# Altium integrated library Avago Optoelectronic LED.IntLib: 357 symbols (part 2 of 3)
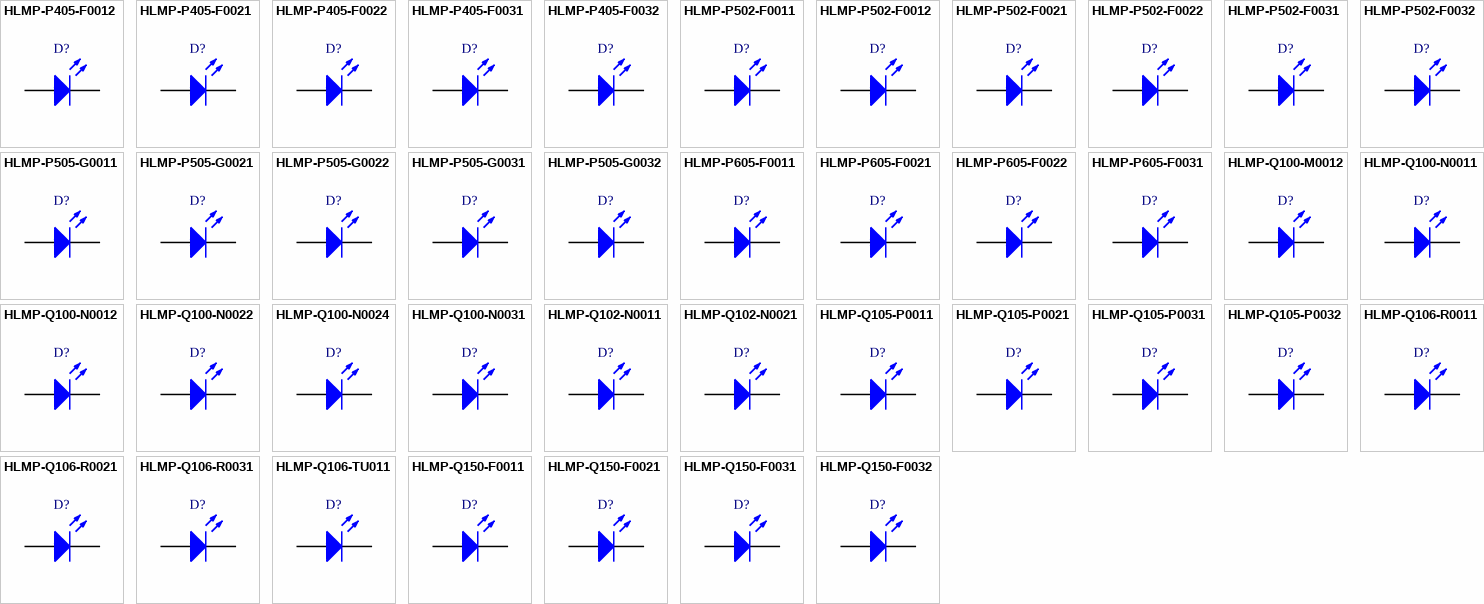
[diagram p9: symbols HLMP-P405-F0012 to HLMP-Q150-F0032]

## HLMP-Q100-N0012
designator D?
Subminiature Red LED Lamp; LuminousIntensity: 25mcd (Minimum).; PCB_Layout: Complies with manufacturer's recommendation.
footprint 2.2X2.1X2.9 (SM LED; 2 Gull Wing Leads; Body 2.2 x 2.1 mm, (LxW))
simulation model Agl_HLMPQ100 (Diode)
signal-integrity model LED
pins: 1 A, 2 K

## HLMP-Q100-N0022
designator D?
Subminiature Red LED Lamp; LuminousIntensity: 25mcd (Minimum).; PCB_Layout: Complies with manufacturer's recommendation.; DrillSize: Nominal, Rounded to nearest 0.05mm
footprint 2.2X2.1X2.9Y (SM LED; 2 Yoke Leads)
simulation model Agl_HLMPQ100 (Diode)
signal-integrity model LED
pins: 1 A, 2 K

## HLMP-Q100-N0024
designator D?
Subminiature Red LED Lamp; LuminousIntensity: 25mcd (Minimum).; PCB_Layout: Complies with manufacturer's recommendation.; DrillSize: Nominal, Rounded to nearest 0.05mm
footprint 2.2X2.1X2.9Y (SM LED; 2 Yoke Leads)
simulation model Agl_HLMPQ100 (Diode)
signal-integrity model LED
pins: 1 A, 2 K

## HLMP-Q100-N0031
designator D?
Subminiature Red LED Lamp; LuminousIntensity: 25mcd (Minimum).; PCB_Layout: Complies with manufacturer's recommendation.; DrillSize: Nominal, Rounded to nearest 0.05mm
footprint 2.2X2.1X2.9Z (SM LED; 2 Z-Bend Leads)
simulation model Agl_HLMPQ100 (Diode)
signal-integrity model LED
pins: 1 A, 2 K

## HLMP-Q102-N0011
designator D?
Subminiature High Performance TS AlGaAs Red LED Lamp; LuminousIntensity: 25mcd (Minimum).; PCB_Layout: Complies with manufacturer's recommendation.
footprint 2.2X2.1X2.9 (SM LED; 2 Gull Wing Leads; Body 2.2 x 2.1 mm, (LxW))
simulation model Agl_HLMPQ102 (Diode)
signal-integrity model LED
pins: 1 A, 2 K

## HLMP-Q102-N0021
designator D?
Subminiature High Performance TS AlGaAs Red LED Lamp; LuminousIntensity: 25mcd (Minimum).; PCB_Layout: Complies with manufacturer's recommendation.; DrillSize: Nominal, Rounded to nearest 0.05mm
footprint 2.2X2.1X2.9Y (SM LED; 2 Yoke Leads)
simulation model Agl_HLMPQ102 (Diode)
signal-integrity model LED
pins: 1 A, 2 K

## HLMP-Q105-P0011
designator D?
Subminiature Red LED Lamp; LuminousIntensity: 40mcd (Minimum).; PCB_Layout: Complies with manufacturer's recommendation.
footprint 2.2X2.1X2.9 (SM LED; 2 Gull Wing Leads; Body 2.2 x 2.1 mm, (LxW))
simulation model Agl_HLMPQ100 (Diode)
signal-integrity model LED
pins: 1 A, 2 K

## HLMP-Q105-P0021
designator D?
Subminiature Red LED Lamp; LuminousIntensity: 40mcd (Minimum).; PCB_Layout: Complies with manufacturer's recommendation.; DrillSize: Nominal, Rounded to nearest 0.05mm
footprint 2.2X2.1X2.9Y (SM LED; 2 Yoke Leads)
simulation model Agl_HLMPQ100 (Diode)
signal-integrity model LED
pins: 1 A, 2 K

## HLMP-Q105-P0031
designator D?
Subminiature Red LED Lamp; LuminousIntensity: 40mcd (Minimum).; PCB_Layout: Complies with manufacturer's recommendation.; DrillSize: Nominal, Rounded to nearest 0.05mm
footprint 2.2X2.1X2.9Z (SM LED; 2 Z-Bend Leads)
simulation model Agl_HLMPQ100 (Diode)
signal-integrity model LED
pins: 1 A, 2 K

## HLMP-Q105-P0032
designator D?
Subminiature Red LED Lamp; LuminousIntensity: 40mcd (Minimum).; PCB_Layout: Complies with manufacturer's recommendation.; DrillSize: Nominal, Rounded to nearest 0.05mm
footprint 2.2X2.1X2.9Z (SM LED; 2 Z-Bend Leads)
simulation model Agl_HLMPQ100 (Diode)
signal-integrity model LED
pins: 1 A, 2 K

## HLMP-Q106-R0011
designator D?
Subminiature High Performance TS AlGaAs Red LED Lamp; LuminousIntensity: 100mcd (Minimum).; PCB_Layout: Complies with manufacturer's recommendation.
footprint 2.2X2.1X2.9 (SM LED; 2 Gull Wing Leads; Body 2.2 x 2.1 mm, (LxW))
simulation model Agl_HLMPQ102 (Diode)
signal-integrity model LED
pins: 1 A, 2 K

## HLMP-Q106-R0021
designator D?
Subminiature High Performance TS AlGaAs Red LED Lamp; LuminousIntensity: 100mcd (Minimum).; PCB_Layout: Complies with manufacturer's recommendation.; DrillSize: Nominal, Rounded to nearest 0.05mm
footprint 2.2X2.1X2.9Y (SM LED; 2 Yoke Leads)
simulation model Agl_HLMPQ102 (Diode)
signal-integrity model LED
pins: 1 A, 2 K

## HLMP-Q106-R0031
designator D?
Subminiature High Performance TS AlGaAs Red LED Lamp; LuminousIntensity: 100mcd (Minimum).; PCB_Layout: Complies with manufacturer's recommendation.; DrillSize: Nominal, Rounded to nearest 0.05mm
footprint 2.2X2.1X2.9Z (SM LED; 2 Z-Bend Leads)
simulation model Agl_HLMPQ102 (Diode)
signal-integrity model LED
pins: 1 A, 2 K

## HLMP-Q106-TU011
designator D?
Subminiature High Performance TS AlGaAs Red LED Lamp; LuminousIntensity: 250mcd (Minimum).; PCB_Layout: Complies with manufacturer's recommendation.
footprint 2.2X2.1X2.9 (SM LED; 2 Gull Wing Leads; Body 2.2 x 2.1 mm, (LxW))
simulation model Agl_HLMPQ102 (Diode)
signal-integrity model LED
pins: 1 A, 2 K

## HLMP-Q150-F0011
designator D?
Subminiature Red LED Lamp; LuminousIntensity: 1mcd (Minimum).; PCB_Layout: Complies with manufacturer's recommendation.
footprint 2.2X2.1X2.9 (SM LED; 2 Gull Wing Leads; Body 2.2 x 2.1 mm, (LxW))
simulation model Agl_HLMPQ150 (Diode)
signal-integrity model LED
pins: 1 A, 2 K

## HLMP-Q150-F0021
designator D?
Subminiature Red LED Lamp; LuminousIntensity: 1mcd (Minimum).; PCB_Layout: Complies with manufacturer's recommendation.; DrillSize: Nominal, Rounded to nearest 0.05mm
footprint 2.2X2.1X2.9Y (SM LED; 2 Yoke Leads)
simulation model Agl_HLMPQ150 (Diode)
signal-integrity model LED
pins: 1 A, 2 K

## HLMP-Q150-F0031
designator D?
Subminiature Red LED Lamp; LuminousIntensity: 1mcd (Minimum).; PCB_Layout: Complies with manufacturer's recommendation.; DrillSize: Nominal, Rounded to nearest 0.05mm
footprint 2.2X2.1X2.9Z (SM LED; 2 Z-Bend Leads)
simulation model Agl_HLMPQ150 (Diode)
signal-integrity model LED
pins: 1 A, 2 K

## HLMP-Q150-F0032
designator D?
Subminiature Red LED Lamp; LuminousIntensity: 1mcd (Minimum).; PCB_Layout: Complies with manufacturer's recommendation.; DrillSize: Nominal, Rounded to nearest 0.05mm
footprint 2.2X2.1X2.9Z (SM LED; 2 Z-Bend Leads)
simulation model Agl_HLMPQ150 (Diode)
signal-integrity model LED
pins: 1 A, 2 K

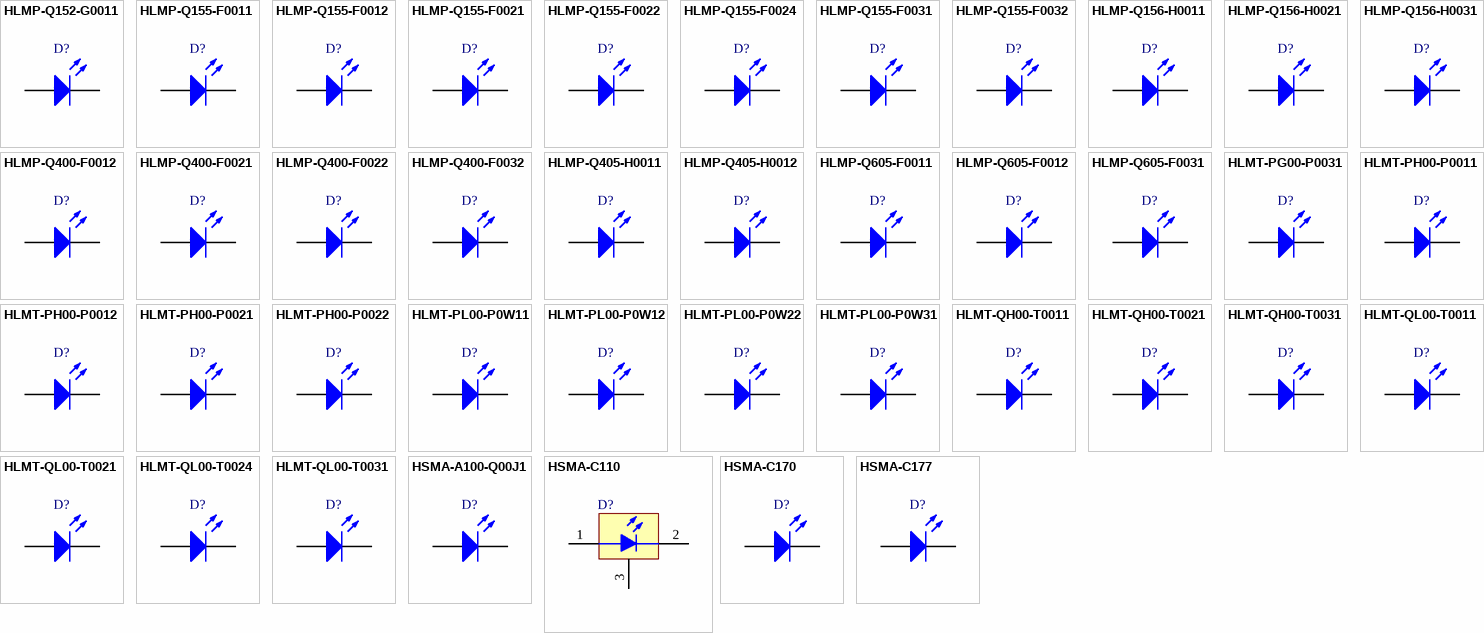
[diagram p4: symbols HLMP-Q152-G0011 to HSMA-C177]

## HLMP-Q152-G0011
designator D?
Subminiature High Performance TS AlGaAs Red LED Lamp; LuminousIntensity: 1mcd (Minimum).; PCB_Layout: Complies with manufacturer's recommendation.
footprint 2.2X2.1X2.9 (SM LED; 2 Gull Wing Leads; Body 2.2 x 2.1 mm, (LxW))
simulation model Agl_HLMPQ152 (Diode)
signal-integrity model LED
pins: 1 A, 2 K

## HLMP-Q155-F0011
designator D?
Subminiature Red LED Lamp; LuminousIntensity: 1mcd (Minimum).; PCB_Layout: Complies with manufacturer's recommendation.
footprint 2.2X2.1X2.9 (SM LED; 2 Gull Wing Leads; Body 2.2 x 2.1 mm, (LxW))
simulation model Agl_HLMPQ150 (Diode)
signal-integrity model LED
pins: 1 A, 2 K

## HLMP-Q155-F0012
designator D?
Subminiature Red LED Lamp; LuminousIntensity: 1mcd (Minimum).; PCB_Layout: Complies with manufacturer's recommendation.
footprint 2.2X2.1X2.9 (SM LED; 2 Gull Wing Leads; Body 2.2 x 2.1 mm, (LxW))
simulation model Agl_HLMPQ150 (Diode)
signal-integrity model LED
pins: 1 A, 2 K

## HLMP-Q155-F0021
designator D?
Subminiature Red LED Lamp; LuminousIntensity: 1mcd (Minimum).; PCB_Layout: Complies with manufacturer's recommendation.; DrillSize: Nominal, Rounded to nearest 0.05mm
footprint 2.2X2.1X2.9Y (SM LED; 2 Yoke Leads)
simulation model Agl_HLMPQ150 (Diode)
signal-integrity model LED
pins: 1 A, 2 K

## HLMP-Q155-F0022
designator D?
Subminiature Red LED Lamp; LuminousIntensity: 1mcd (Minimum).; PCB_Layout: Complies with manufacturer's recommendation.; DrillSize: Nominal, Rounded to nearest 0.05mm
footprint 2.2X2.1X2.9Y (SM LED; 2 Yoke Leads)
simulation model Agl_HLMPQ150 (Diode)
signal-integrity model LED
pins: 1 A, 2 K

## HLMP-Q155-F0024
designator D?
Subminiature Red LED Lamp; LuminousIntensity: 1mcd (Minimum).; PCB_Layout: Complies with manufacturer's recommendation.; DrillSize: Nominal, Rounded to nearest 0.05mm
footprint 2.2X2.1X2.9Y (SM LED; 2 Yoke Leads)
simulation model Agl_HLMPQ150 (Diode)
signal-integrity model LED
pins: 1 A, 2 K

## HLMP-Q155-F0031
designator D?
Subminiature Red LED Lamp; LuminousIntensity: 1mcd (Minimum).; PCB_Layout: Complies with manufacturer's recommendation.; DrillSize: Nominal, Rounded to nearest 0.05mm
footprint 2.2X2.1X2.9Z (SM LED; 2 Z-Bend Leads)
simulation model Agl_HLMPQ150 (Diode)
signal-integrity model LED
pins: 1 A, 2 K

## HLMP-Q155-F0032
designator D?
Subminiature Red LED Lamp; LuminousIntensity: 1mcd (Minimum).; PCB_Layout: Complies with manufacturer's recommendation.; DrillSize: Nominal, Rounded to nearest 0.05mm
footprint 2.2X2.1X2.9Z (SM LED; 2 Z-Bend Leads)
simulation model Agl_HLMPQ150 (Diode)
signal-integrity model LED
pins: 1 A, 2 K

## HLMP-Q156-H0011
designator D?
Subminiature High Performance TS AlGaAs Red LED Lamp; LuminousIntensity: 2.5mcd (Minimum).; PCB_Layout: Complies with manufacturer's recommendation.
footprint 2.2X2.1X2.9 (SM LED; 2 Gull Wing Leads; Body 2.2 x 2.1 mm, (LxW))
simulation model Agl_HLMPQ152 (Diode)
signal-integrity model LED
pins: 1 A, 2 K

## HLMP-Q156-H0021
designator D?
Subminiature High Performance TS AlGaAs Red LED Lamp; LuminousIntensity: 2.5mcd (Minimum).; PCB_Layout: Complies with manufacturer's recommendation.; DrillSize: Nominal, Rounded to nearest 0.05mm
footprint 2.2X2.1X2.9Y (SM LED; 2 Yoke Leads)
simulation model Agl_HLMPQ152 (Diode)
signal-integrity model LED
pins: 1 A, 2 K

## HLMP-Q156-H0031
designator D?
Subminiature High Performance TS AlGaAs Red LED Lamp; LuminousIntensity: 2.5mcd (Minimum).; PCB_Layout: Complies with manufacturer's recommendation.; DrillSize: Nominal, Rounded to nearest 0.05mm
footprint 2.2X2.1X2.9Z (SM LED; 2 Z-Bend Leads)
simulation model Agl_HLMPQ152 (Diode)
signal-integrity model LED
pins: 1 A, 2 K

## HLMP-Q400-F0012
designator D?
Subminiature Orange LED Lamp; LuminousIntensity: 1mcd (Minimum).; PCB_Layout: Complies with manufacturer's recommendation.
footprint 2.2X2.1X2.9 (SM LED; 2 Gull Wing Leads; Body 2.2 x 2.1 mm, (LxW))
simulation model Agl_HLMPQ400 (Diode)
signal-integrity model LED
pins: 1 A, 2 K

## HLMP-Q400-F0021
designator D?
Subminiature Orange LED Lamp; LuminousIntensity: 1mcd (Minimum).; PCB_Layout: Complies with manufacturer's recommendation.; DrillSize: Nominal, Rounded to nearest 0.05mm
footprint 2.2X2.1X2.9Y (SM LED; 2 Yoke Leads)
simulation model Agl_HLMPQ400 (Diode)
signal-integrity model LED
pins: 1 A, 2 K

## HLMP-Q400-F0022
designator D?
Subminiature Orange LED Lamp; LuminousIntensity: 1mcd (Minimum).; PCB_Layout: Complies with manufacturer's recommendation.; DrillSize: Nominal, Rounded to nearest 0.05mm
footprint 2.2X2.1X2.9Y (SM LED; 2 Yoke Leads)
simulation model Agl_HLMPQ400 (Diode)
signal-integrity model LED
pins: 1 A, 2 K

## HLMP-Q400-F0032
designator D?
Subminiature Orange LED Lamp; LuminousIntensity: 1mcd (Minimum).; PCB_Layout: Complies with manufacturer's recommendation.; DrillSize: Nominal, Rounded to nearest 0.05mm
footprint 2.2X2.1X2.9Z (SM LED; 2 Z-Bend Leads)
simulation model Agl_HLMPQ400 (Diode)
signal-integrity model LED
pins: 1 A, 2 K

## HLMP-Q405-H0011
designator D?
Subminiature Orange LED Lamp; LuminousIntensity: 2.5mcd (Minimum).; PCB_Layout: Complies with manufacturer's recommendation.
footprint 2.2X2.1X2.9 (SM LED; 2 Gull Wing Leads; Body 2.2 x 2.1 mm, (LxW))
simulation model Agl_HLMPQ400 (Diode)
signal-integrity model LED
pins: 1 A, 2 K

## HLMP-Q405-H0012
designator D?
Subminiature Orange LED Lamp; LuminousIntensity: 2.5mcd (Minimum).; PCB_Layout: Complies with manufacturer's recommendation.
footprint 2.2X2.1X2.9 (SM LED; 2 Gull Wing Leads; Body 2.2 x 2.1 mm, (LxW))
simulation model Agl_HLMPQ400 (Diode)
signal-integrity model LED
pins: 1 A, 2 K

## HLMP-Q605-F0011
designator D?
Subminiature Green LED Lamp; LuminousIntensity: 1mcd (Minimum).; PCB_Layout: Complies with manufacturer's recommendation.
footprint 2.2X2.1X2.9 (SM LED; 2 Gull Wing Leads; Body 2.2 x 2.1 mm, (LxW))
simulation model Agl_HLMPQ605 (Diode)
signal-integrity model LED
pins: 1 A, 2 K

## HLMP-Q605-F0012
designator D?
Subminiature Green LED Lamp; LuminousIntensity: 1mcd (Minimum).; PCB_Layout: Complies with manufacturer's recommendation.
footprint 2.2X2.1X2.9 (SM LED; 2 Gull Wing Leads; Body 2.2 x 2.1 mm, (LxW))
simulation model Agl_HLMPQ605 (Diode)
signal-integrity model LED
pins: 1 A, 2 K

## HLMP-Q605-F0031
designator D?
Subminiature Green LED Lamp; LuminousIntensity: 1mcd (Minimum).; PCB_Layout: Complies with manufacturer's recommendation.; DrillSize: Nominal, Rounded to nearest 0.05mm
footprint 2.2X2.1X2.9Z (SM LED; 2 Z-Bend Leads)
simulation model Agl_HLMPQ605 (Diode)
signal-integrity model LED
pins: 1 A, 2 K

## HLMT-PG00-P0031
designator D?
Subminiature High Performance TS AlInGaP Red LED Lamp; LuminousIntensity: 40mcd (Minimum).; PCB_Layout: Complies with manufacturer's recommendation.; DrillSize: Nominal, Rounded to nearest 0.05mm
footprint 2.2X2.1X2.2Z (SM LED; 2 Z-Bend Leads)
simulation model Agl_HLMTPH00 (Diode)
signal-integrity model LED
pins: 1 A, 2 K

## HLMT-PH00-P0011
designator D?
Subminiature High Performance TS AlInGaP Red/Orange LED Lamp; LuminousIntensity: 40mcd (Minimum).; LED_Colour: Red & Orange; PCB_Layout: Complies with manufacturer's recommendation.
footprint 2.2X2.1X2.2 (SM LED; 2 Gull Wing Leads; Body 2.2 x 2.1 mm, (LxW))
simulation model Agl_HLMTPH00 (Diode)
signal-integrity model LED
pins: 1 A, 2 K

## HLMT-PH00-P0012
designator D?
Subminiature High Performance TS AlInGaP Red/Orange LED Lamp; LuminousIntensity: 40mcd (Minimum).; LED_Colour: Red & Orange; PCB_Layout: Complies with manufacturer's recommendation.
footprint 2.2X2.1X2.2 (SM LED; 2 Gull Wing Leads; Body 2.2 x 2.1 mm, (LxW))
simulation model Agl_HLMTPH00 (Diode)
signal-integrity model LED
pins: 1 A, 2 K

## HLMT-PH00-P0021
designator D?
Subminiature High Performance AlInGaP Red/Orange LED Lamp; LuminousIntensity: 40mcd (Minimum).; LED_Colour: Red & Orange; PCB_Layout: Complies with manufacturer's recommendation.; DrillSize: Nominal, Rounded to nearest 0.05mm
footprint 2.2X2.1X2.2Y (SM LED; 2 Yoke Leads)
simulation model Agl_HLMTPH00 (Diode)
signal-integrity model LED
pins: 1 A, 2 K

## HLMT-PH00-P0022
designator D?
Subminiature High Performance AlInGaP Red/Orange LED Lamp; LuminousIntensity: 40mcd (Minimum).; LED_Colour: Red & Orange; PCB_Layout: Complies with manufacturer's recommendation.; DrillSize: Nominal, Rounded to nearest 0.05mm
footprint 2.2X2.1X2.2Y (SM LED; 2 Yoke Leads)
simulation model Agl_HLMTPH00 (Diode)
signal-integrity model LED
pins: 1 A, 2 K

## HLMT-PL00-P0W11
designator D?
Subminiature High Performance TS AlInGaP Amber LED Lamp; LuminousIntensity: 40mcd (Minimum).; PCB_Layout: Complies with manufacturer's recommendation.
footprint 2.2X2.1X2.2 (SM LED; 2 Gull Wing Leads; Body 2.2 x 2.1 mm, (LxW))
simulation model Agl_HLMTPH00 (Diode)
signal-integrity model LED
pins: 1 A, 2 K

## HLMT-PL00-P0W12
designator D?
Subminiature High Performance AlInGaP Amber LED Lamp; LuminousIntensity: 40mcd (Minimum).; PCB_Layout: Complies with manufacturer's recommendation.
footprint 2.2X2.1X2.2 (SM LED; 2 Gull Wing Leads; Body 2.2 x 2.1 mm, (LxW))
simulation model Agl_HLMTPH00 (Diode)
signal-integrity model LED
pins: 1 A, 2 K

## HLMT-PL00-P0W22
designator D?
Subminiature High Performance AlInGaP Amber LED Lamp; LuminousIntensity: 40mcd (Minimum).; PCB_Layout: Complies with manufacturer's recommendation.; DrillSize: Nominal, Rounded to nearest 0.05mm
footprint 2.2X2.1X2.2Y (SM LED; 2 Yoke Leads)
simulation model Agl_HLMTPH00 (Diode)
signal-integrity model LED
pins: 1 A, 2 K

## HLMT-PL00-P0W31
designator D?
Subminiature High Performance AlInGaP Amber LED Lamp; LuminousIntensity: 40mcd (Minimum).; PCB_Layout: Complies with manufacturer's recommendation.; DrillSize: Nominal, Rounded to nearest 0.05mm
footprint 2.2X2.1X2.2Z (SM LED; 2 Z-Bend Leads)
simulation model Agl_HLMTPH00 (Diode)
signal-integrity model LED
pins: 1 A, 2 K

## HLMT-QH00-T0011
designator D?
Subminiature High Performance AlInGaP Red/Orange LED Lamp; LuminousIntensity: 250mcd (Minimum).; LED_Colour: Red & Orange; PCB_Layout: Complies with manufacturer's recommendation.
footprint 2.2X2.1X2.9 (SM LED; 2 Gull Wing Leads; Body 2.2 x 2.1 mm, (LxW))
simulation model Agl_HLMTPH00 (Diode)
signal-integrity model LED
pins: 1 A, 2 K

## HLMT-QH00-T0021
designator D?
Subminiature High Performance AlInGaP Red/Orange LED Lamp; LuminousIntensity: 250mcd (Minimum).; LED_Colour: Red & Orange; PCB_Layout: Complies with manufacturer's recommendation.; DrillSize: Nominal, Rounded to nearest 0.05mm
footprint 2.2X2.1X2.9Y (SM LED; 2 Yoke Leads)
simulation model Agl_HLMTPH00 (Diode)
signal-integrity model LED
pins: 1 A, 2 K

## HLMT-QH00-T0031
designator D?
Subminiature High Performance AlInGaP Red/Orange LED Lamp; LuminousIntensity: 250mcd (Minimum).; LED_Colour: Red & Orange; PCB_Layout: Complies with manufacturer's recommendation.; DrillSize: Nominal, Rounded to nearest 0.05mm
footprint 2.2X2.1X2.9Z (SM LED; 2 Z-Bend Leads)
simulation model Agl_HLMTPH00 (Diode)
signal-integrity model LED
pins: 1 A, 2 K

## HLMT-QL00-T0011
designator D?
Subminiature High Performance AlInGaP Amber LED Lamp; LuminousIntensity: 250mcd (Minimum).; PCB_Layout: Complies with manufacturer's recommendation.
footprint 2.2X2.1X2.9 (SM LED; 2 Gull Wing Leads; Body 2.2 x 2.1 mm, (LxW))
simulation model Agl_HLMTPH00 (Diode)
signal-integrity model LED
pins: 1 A, 2 K

## HLMT-QL00-T0021
designator D?
Subminiature High Performance AlInGaP Amber LED Lamp; LuminousIntensity: 250mcd (Minimum).; PCB_Layout: Complies with manufacturer's recommendation.; DrillSize: Nominal, Rounded to nearest 0.05mm
footprint 2.2X2.1X2.9Y (SM LED; 2 Yoke Leads)
simulation model Agl_HLMTPH00 (Diode)
signal-integrity model LED
pins: 1 A, 2 K

## HLMT-QL00-T0024
designator D?
Subminiature High Performance AlInGaP Amber LED Lamp; LuminousIntensity: 250mcd (Minimum).; PCB_Layout: Complies with manufacturer's recommendation.; DrillSize: Nominal, Rounded to nearest 0.05mm
footprint 2.2X2.1X2.9Y (SM LED; 2 Yoke Leads)
simulation model Agl_HLMTPH00 (Diode)
signal-integrity model LED
pins: 1 A, 2 K

## HLMT-QL00-T0031
designator D?
Subminiature High Performance AlInGaP Amber LED Lamp; LuminousIntensity: 250mcd (Minimum).; PCB_Layout: Complies with manufacturer's recommendation.; DrillSize: Nominal, Rounded to nearest 0.05mm
footprint 2.2X2.1X2.9Z (SM LED; 2 Z-Bend Leads)
simulation model Agl_HLMTPH00 (Diode)
signal-integrity model LED
pins: 1 A, 2 K

## HSMA-A100-Q00J1
designator D?
Surface Mount LED Indicator, Amber; LuminousIntensity: 63mcd (Minimum).; PCB_Layout: Complies with manufacturer's recommendation.
footprint 3.5X2.8X1.9 (SM LED; 2 C-Bend Leads; Body 3.5 x 2.8 x 1.9 mm, inc leads (LxWxH typ))
simulation model Agl_HSMAC191 (Diode)
signal-integrity model LED
pins: 1 A, 2 K

## HSMA-C110
designator D?
High Performance Chip LED, Amber; LuminousIntensity: 25mcd (Minimum).; PCB_Layout: Complies with manufacturer's recommendation.
footprint 3.2X1.0X1.5 (SM Right-Angle Mount LED; 3 Leads; Body 3.2 x 1.0 x 1.5 mm (LxWxH))
simulation model Agl_HSMAC191 (Diode)
pins: 1 A, 2 K, 3 Mount

## HSMA-C170
designator D?
High Performance Chip LED, Amber; LuminousIntensity: 25mcd (Minimum).; PCB_Layout: Complies with manufacturer's recommendation.
footprint 2.0X1.25X0.8 (SM LED; 2 Flat Leads)
simulation model Agl_HSMAC191 (Diode)
signal-integrity model LED
pins: 1 A, 2 K

## HSMA-C177
designator D?
Low Profile Chip LED, Amber; LuminousIntensity: 25mcd (Minimum).; PCB_Layout: Complies with manufacturer's recommendation.
footprint 2.1X1.25X0.4 (SM LED; 2 Flat Leads)
simulation model Agl_HSMAC177 (Diode)
signal-integrity model LED
pins: 1 A, 2 K

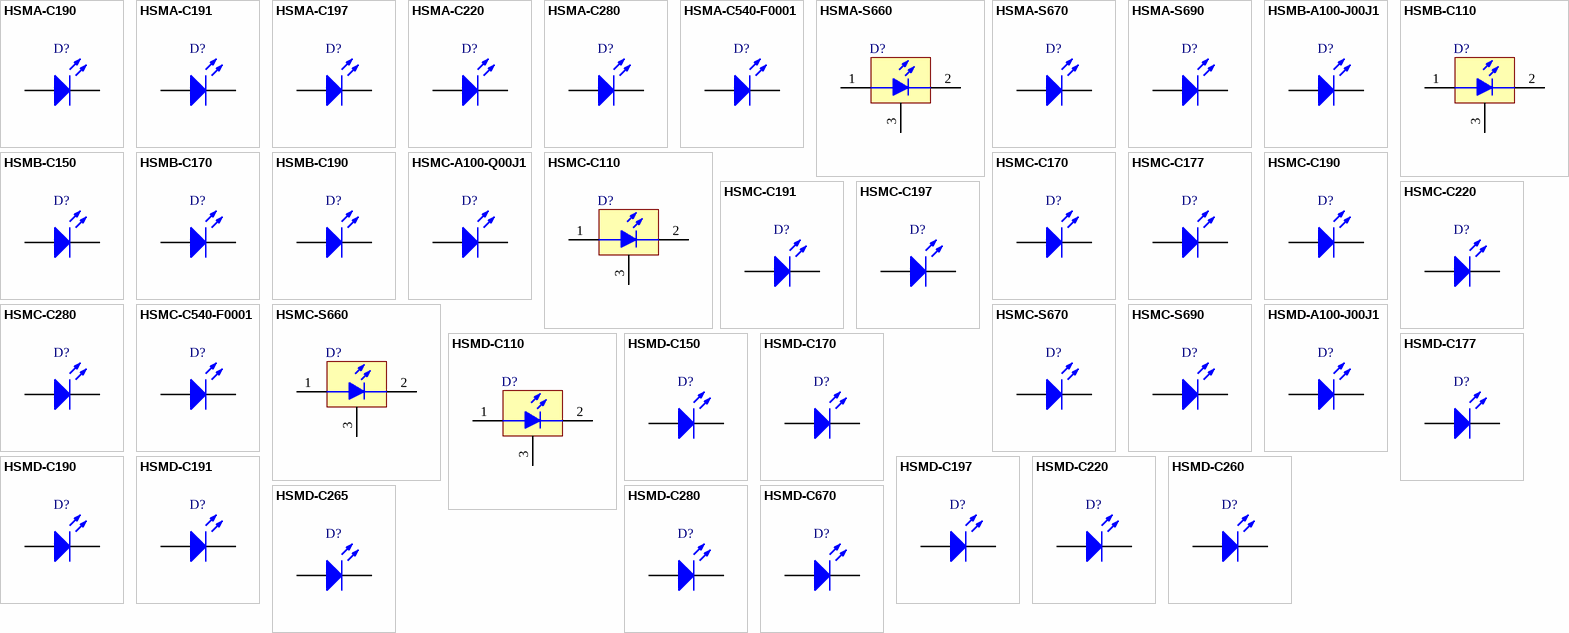
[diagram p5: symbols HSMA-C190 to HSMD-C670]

## HSMA-C190
designator D?
High Performance Chip LED, Amber; LuminousIntensity: 25mcd (Minimum).; PCB_Layout: Complies with manufacturer's recommendation.
footprint 1.6X0.8X0.8 (SM LED; 2 Flat Leads)
simulation model Agl_HSMAC191 (Diode)
signal-integrity model LED
pins: 1 A, 2 K

## HSMA-C191
designator D?
High Performance Chip LED, Amber; LuminousIntensity: 25mcd (Minimum).; PCB_Layout: Complies with manufacturer's recommendation.
footprint 1.6X0.8X0.6 (SM LED; 2 Flat Leads)
simulation model Agl_HSMAC191 (Diode)
signal-integrity model LED
pins: 1 A, 2 K

## HSMA-C197
designator D?
Low Profile Chip LED, Yellow; LuminousIntensity: 2.5mcd (Minimum).; PCB_Layout: Complies with manufacturer's recommendation.
footprint 1.6X0.8X0.4 (SM LED; 2 Flat Leads)
simulation model Agl_HSMAC177 (Diode)
signal-integrity model LED
pins: 1 A, 2 K

## HSMA-C220
designator D?
High Performance Chip LED, Amber; LuminousIntensity: 63mcd (Minimum).; PCB_Layout: Complies with manufacturer's recommendation.
footprint 2.0X1.25X1.2 (SM LED; 2 Flat Leads)
simulation model Agl_HSMAC220 (Diode)
signal-integrity model LED
pins: 1 A, 2 K

## HSMA-C280
designator D?
Miniature Chip LED, Amber; LuminousIntensity: 25mcd (Minimum).; PCB_Layout: Complies with manufacturer's recommendation.
footprint 1.0X0.5X0.4 (SM LED; 2 Flat Leads)
simulation model Agl_HSMAC177 (Diode)
signal-integrity model LED
pins: 1 A, 2 K

## HSMA-C540-F0001
designator D?
Top Mount AS AlInGaP Amber Oval Lens High Brightness; LuminousIntensity: 96mcd (Minimum).; PCB_Layout: Complies with manufacturer's recommendation.
footprint 2.0X1.25X1.2 (SM LED; 2 Flat Leads)
simulation model Agl_HSMAC540 (Diode)
signal-integrity model LED
pins: 1 A, 2 K

## HSMA-S660
designator D?
Right Angle SMT Chip LED, Amber; LuminousIntensity: 16mcd (Minimum).; PCB_Layout: Complies with manufacturer's recommendation.
footprint NA (SM Right-Angle Mount LED; 3 Leads)
simulation model Agl_HSMAC191 (Diode)
pins: 1 A, 2 K, 3 Mount

## HSMA-S670
designator D?
SMT Top Mount Chip LED, Amber; LuminousIntensity: 16mcd (Minimum).; PCB_Layout: Complies with manufacturer's recommendation.
footprint 2.0X1.25X0.8 (SM LED; 2 Flat Leads)
simulation model Agl_HSMAC191 (Diode)
signal-integrity model LED
pins: 1 A, 2 K

## HSMA-S690
designator D?
SMT Top Mount Chip LED, Amber; LuminousIntensity: 16mcd (Minimum).; PCB_Layout: Complies with manufacturer's recommendation.
footprint 1.6X0.8X0.7 (SM LED; 2 Flat Leads)
simulation model Agl_HSMAC191 (Diode)
signal-integrity model LED
pins: 1 A, 2 K

## HSMB-A100-J00J1
designator D?
Surface Mount LED Indicator, Blue; LuminousIntensity: 4mcd (Minimum).; PCB_Layout: Complies with manufacturer's recommendation.
footprint 3.5X2.8X1.9 (SM LED; 2 C-Bend Leads; Body 3.5 x 2.8 x 1.9 mm, inc leads (LxWxH typ))
simulation model Agl_HSMBA100 (Diode)
signal-integrity model LED
pins: 1 A, 2 K

## HSMB-C110
designator D?
Blue Surface Mount Chip LED, Blue; LuminousIntensity: 1.6mcd (Minimum).; PCB_Layout: Complies with manufacturer's recommendation.
footprint 3.2X1.0X1.5 (SM Right-Angle Mount LED; 3 Leads; Body 3.2 x 1.0 x 1.5 mm (LxWxH))
simulation model Agl_HSMBC110 (Diode)
pins: 1 A, 2 K, 3 Mount

## HSMB-C150
designator D?
Blue Surface Mount Chip LED, Blue; LuminousIntensity: 1.6mcd (Minimum).; PCB_Layout: Complies with manufacturer's recommendation.
footprint 3.2X1.6X1.1 (SM LED; 2 Flat Leads)
simulation model Agl_HSMBC110 (Diode)
signal-integrity model LED
pins: 1 A, 2 K

## HSMB-C170
designator D?
Blue Surface Mount Chip LED, Blue; LuminousIntensity: 1.6mcd (Minimum).; PCB_Layout: Complies with manufacturer's recommendation.
footprint 2.0X1.25X0.8 (SM LED; 2 Flat Leads)
simulation model Agl_HSMBC110 (Diode)
signal-integrity model LED
pins: 1 A, 2 K

## HSMB-C190
designator D?
Blue Surface Mount Chip LED, Blue; LuminousIntensity: 1.6mcd (Minimum).; PCB_Layout: Complies with manufacturer's recommendation.
footprint 1.6X0.8X0.8 (SM LED; 2 Flat Leads)
simulation model Agl_HSMBC110 (Diode)
signal-integrity model LED
pins: 1 A, 2 K

## HSMC-A100-Q00J1
designator D?
Surface Mount LED Indicator, Red; LuminousIntensity: 63mcd (Minimum).; PCB_Layout: Complies with manufacturer's recommendation.
footprint 3.5X2.8X1.9 (SM LED; 2 C-Bend Leads; Body 3.5 x 2.8 x 1.9 mm, inc leads (LxWxH typ))
simulation model Agl_HSMAC191 (Diode)
signal-integrity model LED
pins: 1 A, 2 K

## HSMC-C110
designator D?
High Performance Chip LED, Red; LuminousIntensity: 25mcd (Minimum).; PCB_Layout: Complies with manufacturer's recommendation.
footprint 3.2X1.0X1.5 (SM Right-Angle Mount LED; 3 Leads; Body 3.2 x 1.0 x 1.5 mm (LxWxH))
simulation model Agl_HSMAC191 (Diode)
pins: 1 A, 2 K, 3 Mount

## HSMC-C170
designator D?
High Performance Chip LED, Red; LuminousIntensity: 25mcd (Minimum).; PCB_Layout: Complies with manufacturer's recommendation.
footprint 2.0X1.25X0.8 (SM LED; 2 Flat Leads)
simulation model Agl_HSMAC191 (Diode)
signal-integrity model LED
pins: 1 A, 2 K

## HSMC-C177
designator D?
Low Profile Chip LED, Red; LuminousIntensity: 25mcd (Minimum).; PCB_Layout: Complies with manufacturer's recommendation.
footprint 2.0X1.25X0.4 (SM LED; 2 Flat Leads)
simulation model Agl_HSMCC177 (Diode)
signal-integrity model LED
pins: 1 A, 2 K

## HSMC-C190
designator D?
High Performance Chip LED, Red; LuminousIntensity: 25mcd (Minimum).; PCB_Layout: Complies with manufacturer's recommendation.
footprint 1.6X0.8X0.8 (SM LED; 2 Flat Leads)
simulation model Agl_HSMAC191 (Diode)
signal-integrity model LED
pins: 1 A, 2 K

## HSMC-C191
designator D?
High Performance Chip LED, Red; LuminousIntensity: 25mcd (Minimum).; PCB_Layout: Complies with manufacturer's recommendation.
footprint 1.6X0.8X0.6 (SM LED; 2 Flat Leads)
simulation model Agl_HSMAC191 (Diode)
signal-integrity model LED
pins: 1 A, 2 K

## HSMC-C197
designator D?
Low Profile Chip LED, Red; LuminousIntensity: 25mcd (Minimum).; PCB_Layout: Complies with manufacturer's recommendation.
footprint 1.6X0.8X0.4 (SM LED; 2 Flat Leads)
simulation model Agl_HSMCC177 (Diode)
signal-integrity model LED
pins: 1 A, 2 K

## HSMC-C220
designator D?
High Performance Chip LED, Red; LuminousIntensity: 63mcd (Minimum).; PCB_Layout: Complies with manufacturer's recommendation.
footprint 2.0X1.25X1.2 (SM LED; 2 Flat Leads)
simulation model Agl_HSMAC220 (Diode)
signal-integrity model LED
pins: 1 A, 2 K

## HSMC-C280
designator D?
Miniature Chip LED, Red; LuminousIntensity: 25mcd (Minimum).; PCB_Layout: Complies with manufacturer's recommendation.
footprint 1.0X0.5X0.4 (SM LED; 2 Flat Leads)
simulation model Agl_HSMCC177 (Diode)
signal-integrity model LED
pins: 1 A, 2 K

## HSMC-C540-F0001
designator D?
Top Mount AS AlInGaP Red Oval Lens High Brightness; LuminousIntensity: 96mcd (Minimum).; PCB_Layout: Complies with manufacturer's recommendation.
footprint 2.0X1.25X1.2 (SM LED; 2 Flat Leads)
simulation model Agl_HSMAC540 (Diode)
signal-integrity model LED
pins: 1 A, 2 K

## HSMC-S660
designator D?
Right Angle SMT Chip LED, Red; LuminousIntensity: 16mcd (Minimum).; PCB_Layout: Complies with manufacturer's recommendation.
footprint 3.0X1.0X2.0W (SM Right-Angle Mount LED; 3 Leads; Body 3.0 x 1.0 x 2.0 mm (LxWxH))
simulation model Agl_HSMAC191 (Diode)
pins: 1 A, 2 K, 3 Mount

## HSMC-S670
designator D?
SMT Top Mount Chip LED, Red; LuminousIntensity: 16mcd (Minimum).; PCB_Layout: Complies with manufacturer's recommendation.
footprint 2.0X1.25X0.8 (SM LED; 2 Flat Leads)
simulation model Agl_HSMAC191 (Diode)
signal-integrity model LED
pins: 1 A, 2 K

## HSMC-S690
designator D?
SMT Top Mount Chip LED, Red; LuminousIntensity: 16mcd (Minimum).; PCB_Layout: Complies with manufacturer's recommendation.
footprint 1.6X0.8X0.7 (SM LED; 2 Flat Leads)
simulation model Agl_HSMAC191 (Diode)
signal-integrity model LED
pins: 1 A, 2 K

## HSMD-A100-J00J1
designator D?
Surface Mount LED Indicator, Orange; LuminousIntensity: 4mcd (Minimum).; PCB_Layout: Complies with manufacturer's recommendation.
footprint 3.5X2.8X1.9 (SM LED; 2 C-Bend Leads; Body 3.5 x 2.8 x 1.9 mm, inc leads (LxWxH typ))
simulation model Agl_HSMDC110 (Diode)
signal-integrity model LED
pins: 1 A, 2 K

## HSMD-C110
designator D?
Surface Mount Chip LED, Orange; LuminousIntensity: 2.5mcd (Minimum).; PCB_Layout: Complies with manufacturer's recommendation.
footprint 3.2X1.0X1.5 (SM Right-Angle Mount LED; 3 Leads; Body 3.2 x 1.0 x 1.5 mm (LxWxH))
simulation model Agl_HSMDC110 (Diode)
pins: 1 A, 2 K, 3 Mount

## HSMD-C150
designator D?
Surface Mount Chip LED, Orange; LuminousIntensity: 2.5mcd (Minimum).; PCB_Layout: Complies with manufacturer's recommendation.
footprint 3.2X1.6X1.1 (SM LED; 2 Flat Leads)
simulation model Agl_HSMDC110 (Diode)
signal-integrity model LED
pins: 1 A, 2 K

## HSMD-C170
designator D?
Surface Mount Chip LED, Orange; LuminousIntensity: 2.5mcd (Minimum).; PCB_Layout: Complies with manufacturer's recommendation.
footprint 2.0X1.25X0.8 (SM LED; 2 Flat Leads)
simulation model Agl_HSMDC110 (Diode)
signal-integrity model LED
pins: 1 A, 2 K

## HSMD-C177
designator D?
Low Profile Chip LED, Orange; LuminousIntensity: 2.5mcd (Minimum).; PCB_Layout: Complies with manufacturer's recommendation.
footprint 2.0X1.25X0.4 (SM LED; 2 Flat Leads)
simulation model Agl_HSMDC110 (Diode)
signal-integrity model LED
pins: 1 A, 2 K

## HSMD-C190
designator D?
Surface Mount Chip LED, Orange; LuminousIntensity: 2.5mcd (Minimum).; PCB_Layout: Complies with manufacturer's recommendation.
footprint 1.6X0.8X0.8 (SM LED; 2 Flat Leads)
simulation model Agl_HSMDC110 (Diode)
signal-integrity model LED
pins: 1 A, 2 K

## HSMD-C191
designator D?
Low Profile Chip LED, Orange; LuminousIntensity: 2.5mcd (Minimum).; PCB_Layout: Complies with manufacturer's recommendation.
footprint 1.6X0.8X0.6 (SM LED; 2 Flat Leads)
simulation model Agl_HSMDC110 (Diode)
signal-integrity model LED
pins: 1 A, 2 K

## HSMD-C197
designator D?
Low Profile Chip LED, Orange; LuminousIntensity: 2.5mcd (Minimum).; PCB_Layout: Complies with manufacturer's recommendation.
footprint 1.6X0.4X0.4 (SM LED; 2 Flat Leads)
simulation model Agl_HSMDC110 (Diode)
signal-integrity model LED
pins: 1 A, 2 K

## HSMD-C220
designator D?
High Performance Chip LED, Orange; LuminousIntensity: 6.3mcd (Minimum).; PCB_Layout: Complies with manufacturer's recommendation.
footprint 2.0X1.25X1.2 (SM LED; 2 Flat Leads)
simulation model Agl_HSMDC220 (Diode)
signal-integrity model LED
pins: 1 A, 2 K

## HSMD-C260
designator D?
Reverse Mount Chip LED, Orange; LuminousIntensity: 2.5mcd (Minimum).; PCB_Layout: Complies with manufacturer's recommendation.; DrillSize: Nominal, Rounded to nearest 0.05mm
footprint 3.4X1.25X1.1 (SM Reverse Mount LED; 2 Flat Leads)
simulation model Agl_HSMYC110 (Diode)
signal-integrity model LED
pins: 1 A, 2 K

## HSMD-C265
designator D?
Reverse Mount Chip LED, Orange; LuminousIntensity: 2.5mcd (Minimum).; PCB_Layout: Complies with manufacturer's recommendation.; DrillSize: Nominal, Rounded to nearest 0.05mm
footprint 3.4X1.25X1.1 (SM Reverse Mount LED; 2 Flat Leads)
simulation model Agl_HSMDC265 (Diode)
signal-integrity model LED
pins: 1 A, 2 K

## HSMD-C280
designator D?
Miniature Chip LED, Orange; LuminousIntensity: 2.5mcd (Minimum).; PCB_Layout: Complies with manufacturer's recommendation.
footprint 1.0X0.5X0.4 (SM LED; 2 Flat Leads)
simulation model Agl_HSMDC110 (Diode)
signal-integrity model LED
pins: 1 A, 2 K

## HSMD-C670
designator D?
SMT Top Mount Chip LED, Orange; LuminousIntensity: 1.6mcd (Minimum).; PCB_Layout: Complies with manufacturer's recommendation.
footprint 2.0X1.25X1.1 (SM LED; 2 Flat Leads)
simulation model Agl_HSMDC650 (Diode)
signal-integrity model LED
pins: 1 A, 2 K

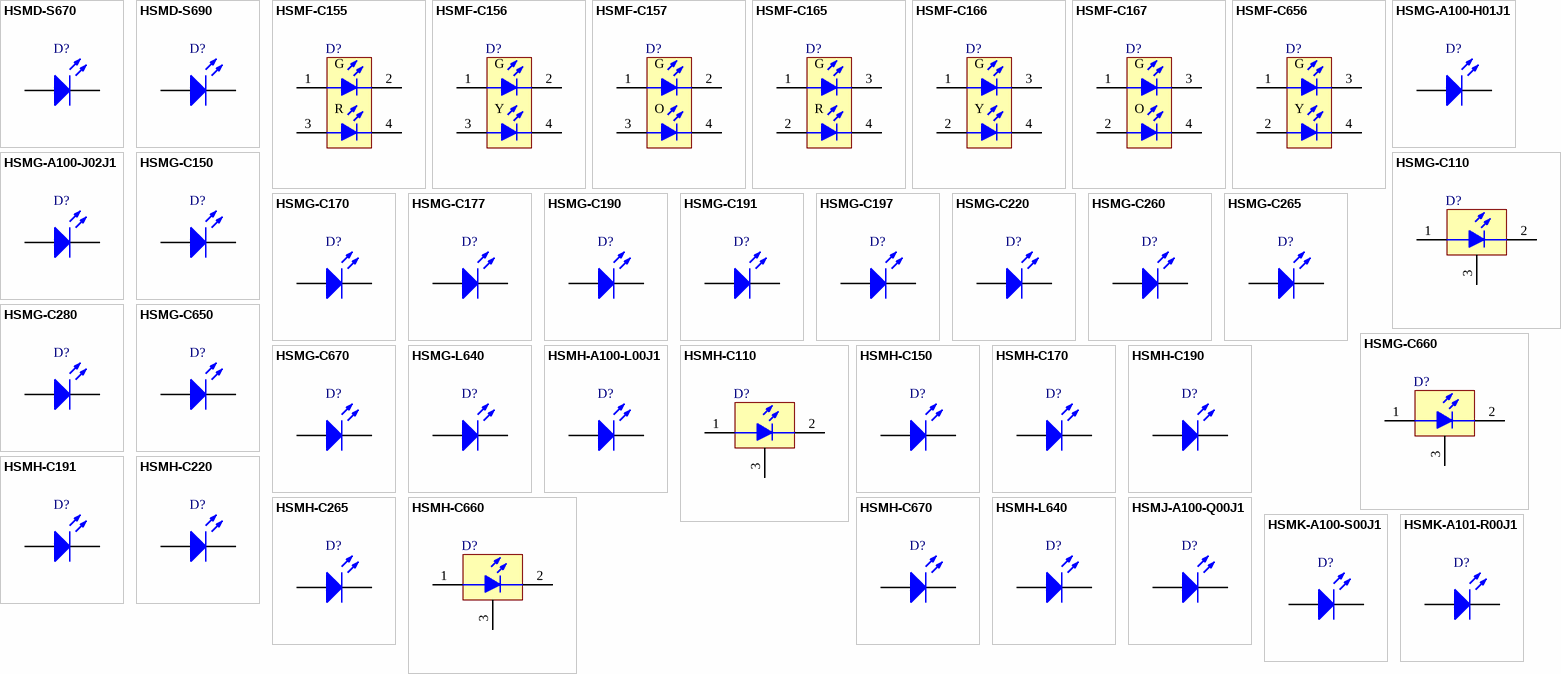
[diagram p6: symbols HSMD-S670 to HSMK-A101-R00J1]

## HSMD-S670
designator D?
High Performance SMT Chip LED, Orange; LuminousIntensity: 16mcd (Minimum).; PCB_Layout: Complies with manufacturer's recommendation.
footprint 2.0X1.25X0.8 (SM LED; 2 Flat Leads)
simulation model Agl_HSMAC191 (Diode)
signal-integrity model LED
pins: 1 A, 2 K

## HSMD-S690
designator D?
High Performance SMT Chip LED, Orange; LuminousIntensity: 16mcd (Minimum).; PCB_Layout: Complies with manufacturer's recommendation.
footprint 1.6X0.8X0.7 (SM LED; 2 Flat Leads)
simulation model Agl_HSMAC191 (Diode)
signal-integrity model LED
pins: 1 A, 2 K

## HSMF-C155
designator D?
Surface Mount Chip LED (Red/Green); LuminousIntensity: 4mcd (Minimum).; LED_Colour: Red & Green; PCB_Layout: Complies with manufacturer's recommendation.
footprint 3.2X2.7X1.1 (SM LED, Bi-Colour; 4 Flat Leads; Body 3.2 x 2.7 x 1.1 mm (LxWxH))
simulation model Agl_HSMFC155 (SUBCKT)
signal-integrity model Bicolour LED
pins: 1 A1, 2 K1, 3 A2, 4 K2

## HSMF-C156
designator D?
Surface Mount Chip LED (Yellow/Green); LuminousIntensity: 4mcd (Minimum).; LED_Colour: Yellow & Green; PCB_Layout: Complies with manufacturer's recommendation.
footprint 3.2X2.7X1.1 (SM LED, Bi-Colour; 4 Flat Leads; Body 3.2 x 2.7 x 1.1 mm (LxWxH))
simulation model Agl_HSMFC156 (SUBCKT)
pins: 1 A1, 2 K1, 3 A2, 4 K2

## HSMF-C157
designator D?
Surface Mount Chip LED (Orange/Green); LuminousIntensity: 2.5mcd (Minimum).; LED_Colour: Orange & Green; PCB_Layout: Complies with manufacturer's recommendation.
footprint 3.2X2.7X1.1 (SM LED, Bi-Colour; 4 Flat Leads; Body 3.2 x 2.7 x 1.1 mm (LxWxH))
simulation model Agl_HSMFC157 (SUBCKT)
signal-integrity model Bicolour LED
pins: 1 A1, 2 K1, 3 A2, 4 K2

## HSMF-C165
designator D?
Miniature Bi-Colour Surface Mount Chip LED (Red/Green); LuminousIntensity: 2.5mcd (Minimum).; LED_Colour: Red & Green; PCB_Layout: Complies with manufacturer's recommendation.
footprint 1.6X0.8X0.5 (SM LED, Bi-Colour; 4 Flat Leads; Body 1.6 x 0.8 x 0.5 mm (LxWxH))
simulation model Agl_HSMFC155 (SUBCKT)
signal-integrity model Bicolour LED
pins: 1 A1, 2 A2, 3 K1, 4 K2

## HSMF-C166
designator D?
Miniature Bi-Colour Surface Mount Chip LED (Yellow/Green); LuminousIntensity: 2.5mcd (Minimum).; LED_Colour: Yellow & Green; PCB_Layout: Complies with manufacturer's recommendation.
footprint 1.6X0.8X0.5 (SM LED, Bi-Colour; 4 Flat Leads; Body 1.6 x 0.8 x 0.5 mm (LxWxH))
simulation model Agl_HSMFC156 (SUBCKT)
signal-integrity model Bicolour LED
pins: 1 A1, 2 A2, 3 K1, 4 K2

## HSMF-C167
designator D?
Miniature Bi-Colour Surface Mount Chip LED (Orange/Green); LuminousIntensity: 2.5mcd (Minimum).; LED_Colour: Orange & Green; PCB_Layout: Complies with manufacturer's recommendation.
footprint 1.6X0.8X0.5 (SM LED, Bi-Colour; 4 Flat Leads; Body 1.6 x 0.8 x 0.5 mm (LxWxH))
simulation model Agl_HSMFC157 (SUBCKT)
signal-integrity model Bicolour LED
pins: 1 A1, 2 A2, 3 K1, 4 K2

## HSMF-C656
designator D?
SMT Bi-Colour Chip LED (Yellow/Green); LuminousIntensity: 1.6mcd (Minimum).; LED_Colour: Yellow & Green; PCB_Layout: Complies with manufacturer's recommendation.
footprint 3.2X2.7X1.1A (SM LED, Bi-Colour; 4 Flat Leads; Body 3.2 x 2.7 x 1.1 mm (LxWxH))
simulation model Agl_HSMFC656 (SUBCKT)
signal-integrity model Bicolour LED
pins: 1 A1, 2 A2, 3 K1, 4 K2

## HSMG-A100-H01J1
designator D?
Surface Mount LED Indicator, Green; LuminousIntensity: 4mcd (Minimum).; PCB_Layout: Complies with manufacturer's recommendation.
footprint 3.5X2.8X1.9 (SM LED; 2 C-Bend Leads; Body 3.5 x 2.8 x 1.9 mm, inc leads (LxWxH typ))
simulation model Agl_HSMDC110 (Diode)
signal-integrity model LED
pins: 1 A, 2 K

## HSMG-A100-J02J1
designator D?
Surface Mount LED Indicator, Green; LuminousIntensity: 4mcd (Minimum).; PCB_Layout: Complies with manufacturer's recommendation.
footprint 3.5X2.8X1.9 (SM LED; 2 C-Bend Leads; Body 3.5 x 2.8 x 1.9 mm, inc leads (LxWxH typ))
simulation model Agl_HSMDC110 (Diode)
signal-integrity model LED
pins: 1 A, 2 K

## HSMG-C110
designator D?
Surface Mount Chip LED, Green; LuminousIntensity: 4mcd (Minimum).; PCB_Layout: Complies with manufacturer's recommendation.
footprint 3.2X1.0X1.5 (SM Right-Angle Mount LED; 3 Leads; Body 3.2 x 1.0 x 1.5 mm (LxWxH))
simulation model Agl_HSMGC110 (Diode)
pins: 1 A, 2 K, 3 Mount

## HSMG-C150
designator D?
Surface Mount Chip LED, Green; LuminousIntensity: 4mcd (Minimum).; PCB_Layout: Complies with manufacturer's recommendation.
footprint 3.2X1.6X1.1 (SM LED; 2 Flat Leads)
simulation model Agl_HSMGC110 (Diode)
signal-integrity model LED
pins: 1 A, 2 K

## HSMG-C170
designator D?
Surface Mount Chip LED, Green; LuminousIntensity: 4mcd (Minimum).; PCB_Layout: Complies with manufacturer's recommendation.
footprint 2.0X1.25X0.8 (SM LED; 2 Flat Leads)
simulation model Agl_HSMGC110 (Diode)
signal-integrity model LED
pins: 1 A, 2 K

## HSMG-C177
designator D?
Low Profile Chip LED, Green; LuminousIntensity: 4mcd (Minimum).; PCB_Layout: Complies with manufacturer's recommendation.
footprint 2.0X1.25X0.4 (SM LED; 2 Flat Leads)
simulation model Agl_HSMGC110 (Diode)
signal-integrity model LED
pins: 1 A, 2 K

## HSMG-C190
designator D?
Surface Mount Chip LED, Green; LuminousIntensity: 4mcd (Minimum).; PCB_Layout: Complies with manufacturer's recommendation.
footprint 1.6X0.8X0.8 (SM LED; 2 Flat Leads)
simulation model Agl_HSMGC110 (Diode)
signal-integrity model LED
pins: 1 A, 2 K

## HSMG-C191
designator D?
Low Profile Chip LED, Green; LuminousIntensity: 4mcd (Minimum).; PCB_Layout: Complies with manufacturer's recommendation.
footprint 1.6X0.8X0.6 (SM LED; 2 Flat Leads)
simulation model Agl_HSMGC110 (Diode)
signal-integrity model LED
pins: 1 A, 2 K

## HSMG-C197
designator D?
Low Profile Chip LED, Green; LuminousIntensity: 4mcd (Minimum).; PCB_Layout: Complies with manufacturer's recommendation.
footprint 1.6X0.8X0.4 (SM LED; 2 Flat Leads)
simulation model Agl_HSMGC110 (Diode)
signal-integrity model LED
pins: 1 A, 2 K

## HSMG-C220
designator D?
High Performance Chip LED, Green; LuminousIntensity: 10mcd (Minimum).; PCB_Layout: Complies with manufacturer's recommendation.
footprint 2.0X1.25X1.2 (SM LED; 2 Flat Leads)
simulation model Agl_HSMDC110 (Diode)
signal-integrity model LED
pins: 1 A, 2 K

## HSMG-C260
designator D?
Reverse Mount Chip LED, Green; LuminousIntensity: 4mcd (Minimum).; PCB_Layout: Complies with manufacturer's recommendation.; DrillSize: Nominal, Rounded to nearest 0.05mm
footprint 3.4X1.25X1.1 (SM Reverse Mount LED; 2 Flat Leads)
simulation model Agl_HSMDC265 (Diode)
signal-integrity model LED
pins: 1 A, 2 K

## HSMG-C265
designator D?
Reverse Mount Chip LED, Green; LuminousIntensity: 4mcd (Minimum).; PCB_Layout: Complies with manufacturer's recommendation.; DrillSize: Nominal, Rounded to nearest 0.05mm
footprint 3.4X1.25X1.1 (SM Reverse Mount LED; 2 Flat Leads)
simulation model Agl_HSMDC265 (Diode)
signal-integrity model LED
pins: 1 A, 2 K

## HSMG-C280
designator D?
Miniature Chip LED, Green; LuminousIntensity: 4mcd (Minimum).; PCB_Layout: Complies with manufacturer's recommendation.
footprint 1.0X0.5X0.4 (SM LED; 2 Flat Leads)
simulation model Agl_HSMGC110 (Diode)
signal-integrity model LED
pins: 1 A, 2 K

## HSMG-C650
designator D?
SMT Top Mount Chip LED, Green; LuminousIntensity: 4mcd (Minimum).; PCB_Layout: Complies with manufacturer's recommendation.
footprint 3.2X1.6X1.1 (SM LED; 2 Flat Leads)
simulation model Agl_HSMGC650 (Diode)
signal-integrity model LED
pins: 1 A, 2 K

## HSMG-C660
designator D?
Right Angle SMT Chip LED, Green; LuminousIntensity: 4mcd (Minimum).; PCB_Layout: Complies with manufacturer's recommendation.
footprint 3.0X1.0X2.0W (SM Right-Angle Mount LED; 3 Leads; Body 3.0 x 1.0 x 2.0 mm (LxWxH))
simulation model Agl_HSMGC650 (Diode)
pins: 1 A, 2 K, 3 Mount

## HSMG-C670
designator D?
SMT Top Mount Chip LED, Green; LuminousIntensity: 4mcd (Minimum).; PCB_Layout: Complies with manufacturer's recommendation.
footprint 2.0X1.25X1.1 (SM LED; 2 Flat Leads)
simulation model Agl_HSMGC650 (Diode)
signal-integrity model LED
pins: 1 A, 2 K

## HSMG-L640
designator D?
SMT Top Mount Chip LED, Green; LuminousIntensity: 10mcd (Minimum).; PCB_Layout: Complies with manufacturer's recommendation.
footprint 3.0X1.5X1.5 (SM LED; 2 Flat Leads)
simulation model Agl_HSMGC650 (Diode)
signal-integrity model LED
pins: 1 A, 2 K

## HSMH-A100-L00J1
designator D?
Surface Mount LED Indicator, Red; LuminousIntensity: 10mcd (Minimum).; PCB_Layout: Complies with manufacturer's recommendation.; Note: Anode mark shown on package.
footprint 3.5X2.8X1.9A (SM LED; 2 C-Bend Leads; Body 3.5 x 2.8 x 1.9 mm, inc leads (LxWxH typ))
simulation model Agl_HSMAC191 (Diode)
signal-integrity model LED
pins: 1 A, 2 K

## HSMH-C110
designator D?
Surface Mount Chip LED, Red; LuminousIntensity: 6.3mcd (Minimum).; PCB_Layout: Complies with manufacturer's recommendation.; Note: Anode mark shown on package.
footprint 3.2X1.0X1.5A (SM Right-Angle Mount LED; 3 Leads; Body 3.2 x 1.0 x 1.5 mm (LxWxH))
simulation model Agl_HSMHC110 (Diode)
pins: 1 A, 2 K, 3 Mount

## HSMH-C150
designator D?
Surface Mount Chip LED, Red; LuminousIntensity: 6.3mcd (Minimum).; PCB_Layout: Complies with manufacturer's recommendation.; Note: Anode mark shown on package.
footprint 3.2X1.6X1.1A (SM LED; 2 Flat Leads)
simulation model Agl_HSMHC110 (Diode)
signal-integrity model LED
pins: 1 A, 2 K

## HSMH-C170
designator D?
Surface Mount Chip LED, Red; LuminousIntensity: 6.3mcd (Minimum).; PCB_Layout: Complies with manufacturer's recommendation.; Note: Anode mark shown on package.
footprint 2.0X1.25X0.8A (SM LED; 2 Flat Leads)
simulation model Agl_HSMHC110 (Diode)
signal-integrity model LED
pins: 1 A, 2 K

## HSMH-C190
designator D?
Surface Mount Chip LED, Red; LuminousIntensity: 6.3mcd (Minimum).; PCB_Layout: Complies with manufacturer's recommendation.; Note: Anode mark shown on package.
footprint 1.6X0.8X0.8A (SM LED; 2 Flat Leads)
simulation model Agl_HSMHC110 (Diode)
signal-integrity model LED
pins: 1 A, 2 K

## HSMH-C191
designator D?
Low Profile Chip LED, Red; LuminousIntensity: 6.3mcd (Minimum).; PCB_Layout: Complies with manufacturer's recommendation.; Note: Polarity Reversed.
footprint 1.6X0.8X0.8A (SM LED; 2 Flat Leads)
simulation model Agl_HSMHC110 (Diode)
signal-integrity model LED
pins: 1 A, 2 K

## HSMH-C220
designator D?
High Performance Chip LED, Red; LuminousIntensity: 25mcd (Minimum).; PCB_Layout: Complies with manufacturer's recommendation.
footprint 2.0X1.25X1.2 (SM LED; 2 Flat Leads)
simulation model Agl_HSMHC220 (Diode)
signal-integrity model LED
pins: 1 A, 2 K

## HSMH-C265
designator D?
Reverse Mount Chip LED, Red; LuminousIntensity: 6.3mcd (Minimum).; PCB_Layout: Complies with manufacturer's recommendation.; DrillSize: Nominal, Rounded to nearest 0.05mm; Note: Anode mark shown on package.
footprint 3.4X1.25X1.1A (SM Reverse Mount LED; 2 Flat Leads)
simulation model Agl_HSMHC110 (Diode)
signal-integrity model LED
pins: 1 A, 2 K

## HSMH-C660
designator D?
Right Angle SMT Chip LED, Red; LuminousIntensity: 6.3mcd (Minimum).; PCB_Layout: Complies with manufacturer's recommendation.
footprint 3.0X1.0X2.0W (SM Right-Angle Mount LED; 3 Leads; Body 3.0 x 1.0 x 2.0 mm (LxWxH))
simulation model Agl_HSMHC660 (Diode)
pins: 1 A, 2 K, 3 Mount

## HSMH-C670
designator D?
SMT Top Mount Chip LED, Red; LuminousIntensity: 6.3mcd (Minimum).; PCB_Layout: Complies with manufacturer's recommendation.
footprint 2.0X1.25X1.1 (SM LED; 2 Flat Leads)
simulation model Agl_HSMHC650 (Diode)
signal-integrity model LED
pins: 1 A, 2 K

## HSMH-L640
designator D?
SMT Top Mount Chip LED, Red; LuminousIntensity: 10mcd (Minimum).; PCB_Layout: Complies with manufacturer's recommendation.
footprint 3.0X1.5X1.5 (SM LED; 2 Flat Leads)
simulation model Agl_HSMHC660 (Diode)
signal-integrity model LED
pins: 1 A, 2 K

## HSMJ-A100-Q00J1
designator D?
Surface Mount LED Indicator (Red/Orange); LuminousIntensity: 63mcd (Minimum).; LED_Colour: Red & Orange; PCB_Layout: Complies with manufacturer's recommendation.
footprint 3.5X2.8X1.9 (SM LED; 2 C-Bend Leads; Body 3.5 x 2.8 x 1.9 mm, inc leads (LxWxH typ))
simulation model Agl_HSMAC191 (Diode)
signal-integrity model LED
pins: 1 A, 2 K

## HSMK-A100-S00J1
designator D?
Surface Mount LED Indicator, Cyan; LuminousIntensity: 160mcd (Minimum).; PCB_Layout: Complies with manufacturer's recommendation.
footprint 3.5X2.8X1.9 (SM LED; 2 C-Bend Leads; Body 3.5 x 2.8 x 1.9 mm, inc leads (LxWxH typ))
simulation model Agl_HSMKA100 (Diode)
signal-integrity model LED
pins: 1 A, 2 K

## HSMK-A101-R00J1
designator D?
Surface Mount LED Indicator, Cyan; LuminousIntensity: 100mcd (Minimum).; PCB_Layout: Complies with manufacturer's recommendation.
footprint 3.5X2.8X1.9 (SM LED; 2 C-Bend Leads; Body 3.5 x 2.8 x 1.9 mm, inc leads (LxWxH typ))
simulation model Agl_HSMKA100 (Diode)
signal-integrity model LED
pins: 1 A, 2 K

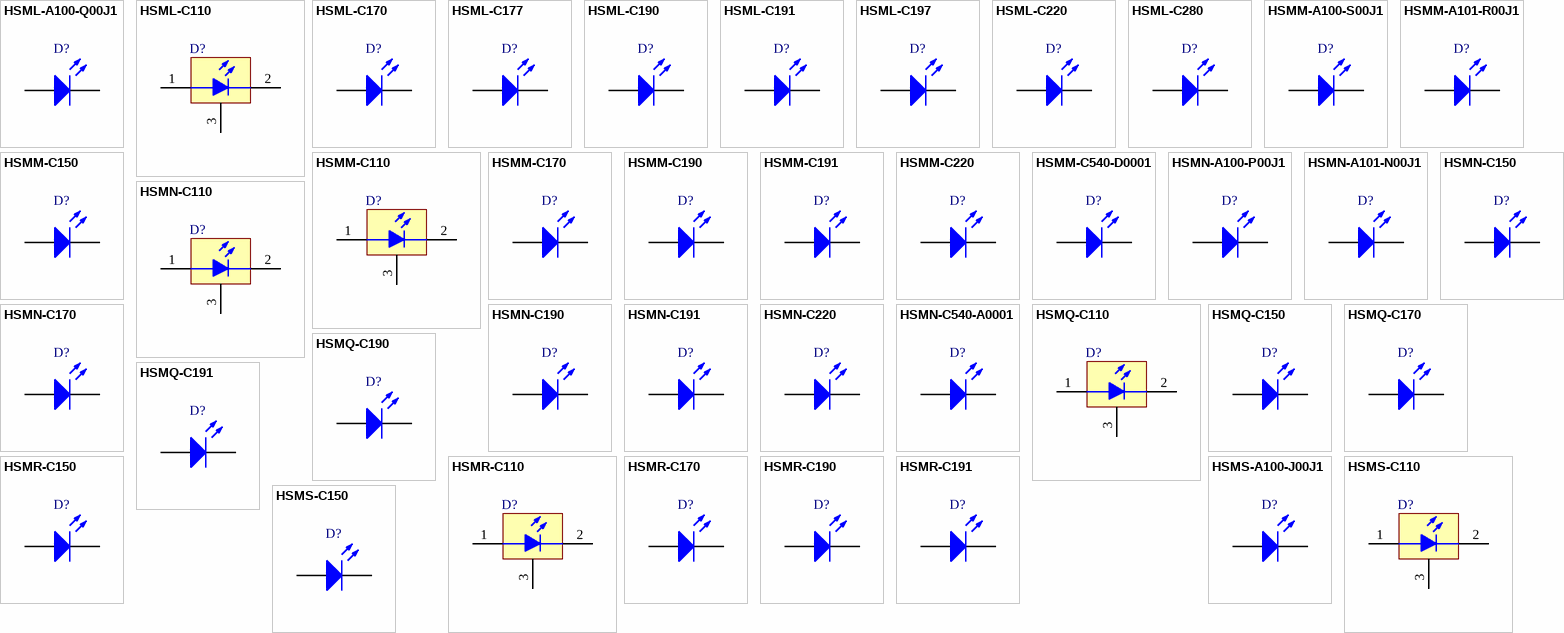
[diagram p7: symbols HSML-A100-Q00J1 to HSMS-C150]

## HSML-A100-Q00J1
designator D?
Surface Mount LED Indicator, Orange; LuminousIntensity: 63mcd (Minimum).; PCB_Layout: Complies with manufacturer's recommendation.
footprint 3.5X2.8X1.9 (SM LED; 2 C-Bend Leads; Body 3.5 x 2.8 x 1.9 mm, inc leads (LxWxH typ))
simulation model Agl_HSMAC191 (Diode)
signal-integrity model LED
pins: 1 A, 2 K

## HSML-C110
designator D?
High Performance Chip LED, Orange; LuminousIntensity: 25mcd (Minimum).; PCB_Layout: Complies with manufacturer's recommendation.
footprint 3.2X1.0X1.5 (SM Right-Angle Mount LED; 3 Leads; Body 3.2 x 1.0 x 1.5 mm (LxWxH))
simulation model Agl_HSMAC191 (Diode)
pins: 1 A, 2 K, 3 Mount

## HSML-C170
designator D?
High Performance Chip LED, Orange; LuminousIntensity: 25mcd (Minimum).; PCB_Layout: Complies with manufacturer's recommendation.
footprint 2.0X1.25X0.8 (SM LED; 2 Flat Leads)
simulation model Agl_HSMAC191 (Diode)
signal-integrity model LED
pins: 1 A, 2 K

## HSML-C177
designator D?
Low Profile Chip LED, Orange; LuminousIntensity: 25mcd (Minimum).; PCB_Layout: Complies with manufacturer's recommendation.
footprint 2.0X1.25X0.4 (SM LED; 2 Flat Leads)
simulation model Agl_HSMLC177 (Diode)
signal-integrity model LED
pins: 1 A, 2 K

## HSML-C190
designator D?
High Performance Chip LED, Orange; LuminousIntensity: 25mcd (Minimum).; PCB_Layout: Complies with manufacturer's recommendation.
footprint 1.6X0.8X0.8 (SM LED; 2 Flat Leads)
simulation model Agl_HSMAC191 (Diode)
signal-integrity model LED
pins: 1 A, 2 K

## HSML-C191
designator D?
High Performance Chip LED, Orange; LuminousIntensity: 25mcd (Minimum).; PCB_Layout: Complies with manufacturer's recommendation.
footprint 1.6X0.8X0.6 (SM LED; 2 Flat Leads)
simulation model Agl_HSMAC191 (Diode)
signal-integrity model LED
pins: 1 A, 2 K

## HSML-C197
designator D?
Low Profile Chip LED, Orange; LuminousIntensity: 25mcd (Minimum).; PCB_Layout: Complies with manufacturer's recommendation.
footprint 1.6X0.8X0.4 (SM LED; 2 Flat Leads)
simulation model Agl_HSMLC177 (Diode)
signal-integrity model LED
pins: 1 A, 2 K

## HSML-C220
designator D?
High Performance Chip LED, Orange; LuminousIntensity: 63mcd (Minimum).; PCB_Layout: Complies with manufacturer's recommendation.
footprint 2.0X1.25X1.2 (SM LED; 2 Flat Leads)
simulation model Agl_HSMLC220 (Diode)
signal-integrity model LED
pins: 1 A, 2 K

## HSML-C280
designator D?
Miniature Chip LED, Orange; LuminousIntensity: 25mcd (Minimum).; PCB_Layout: Complies with manufacturer's recommendation.
footprint 1.0X0.5X0.4 (SM LED; 2 Flat Leads)
simulation model Agl_HSMLC177 (Diode)
signal-integrity model LED
pins: 1 A, 2 K

## HSMM-A100-S00J1
designator D?
Surface Mount LED Indicator, Green; LuminousIntensity: 160mcd (Minimum).; PCB_Layout: Complies with manufacturer's recommendation.
footprint 3.5X2.8X1.9 (SM LED; 2 C-Bend Leads; Body 3.5 x 2.8 x 1.9 mm, inc leads (LxWxH typ))
simulation model Agl_HSMKA100 (Diode)
signal-integrity model LED
pins: 1 A, 2 K

## HSMM-A101-R00J1
designator D?
Surface Mount LED Indicator, Green; LuminousIntensity: 100mcd (Minimum).; PCB_Layout: Complies with manufacturer's recommendation.
footprint 3.5X2.8X1.9 (SM LED; 2 C-Bend Leads; Body 3.5 x 2.8 x 1.9 mm, inc leads (LxWxH typ))
simulation model Agl_HSMKA100 (Diode)
signal-integrity model LED
pins: 1 A, 2 K

## HSMM-C110
designator D?
High Performance SMT Chip LED, Green; LuminousIntensity: 40mcd (Minimum).; PCB_Layout: Complies with manufacturer's recommendation.
footprint 3.2X1.0X1.5 (SM Right-Angle Mount LED; 3 Leads; Body 3.2 x 1.0 x 1.5 mm (LxWxH))
simulation model Agl_HSMMC110 (Diode)
pins: 1 A, 2 K, 3 Mount

## HSMM-C150
designator D?
High Performance SMT Chip LED, Green; LuminousIntensity: 40mcd (Minimum).; PCB_Layout: Complies with manufacturer's recommendation.
footprint 3.2X1.6X1.1 (SM LED; 2 Flat Leads)
simulation model Agl_HSMMC110 (Diode)
signal-integrity model LED
pins: 1 A, 2 K

## HSMM-C170
designator D?
High Performance SMT Chip LED, Green; LuminousIntensity: 40mcd (Minimum).; PCB_Layout: Complies with manufacturer's recommendation.
footprint 2.0X1.25X0.8 (SM LED; 2 Flat Leads)
simulation model Agl_HSMMC110 (Diode)
signal-integrity model LED
pins: 1 A, 2 K

## HSMM-C190
designator D?
High Performance SMT Chip LED, Green; LuminousIntensity: 40mcd (Minimum).; PCB_Layout: Complies with manufacturer's recommendation.
footprint 1.6X0.8X0.8 (SM LED; 2 Flat Leads)
simulation model Agl_HSMMC110 (Diode)
signal-integrity model LED
pins: 1 A, 2 K

## HSMM-C191
designator D?
High Performance SMT Chip LED, Green; LuminousIntensity: 40mcd (Minimum).; PCB_Layout: Complies with manufacturer's recommendation.
footprint 1.6X0.8X0.6 (SM LED; 2 Flat Leads)
simulation model Agl_HSMMC110 (Diode)
signal-integrity model LED
pins: 1 A, 2 K

## HSMM-C220
designator D?
High Performance Chip LED, Green; LuminousIntensity: 63mcd (Minimum).; PCB_Layout: Complies with manufacturer's recommendation.
footprint 2.0X1.25X1.2 (SM LED; 2 Flat Leads)
simulation model Agl_HSMMC220 (Diode)
signal-integrity model LED
pins: 1 A, 2 K

## HSMM-C540-D0001
designator D?
Top Mount InGaN Green Oval Lens High Brightness; LuminousIntensity: 57mcd (Minimum).; PCB_Layout: Complies with manufacturer's recommendation.
footprint 2.0X1.25X1.2 (SM LED; 2 Flat Leads)
simulation model Agl_HSMMC540 (Diode)
signal-integrity model LED
pins: 1 A, 2 K

## HSMN-A100-P00J1
designator D?
Surface Mount LED Indicator, Blue; LuminousIntensity: 40mcd (Minimum).; PCB_Layout: Complies with manufacturer's recommendation.
footprint 3.5X2.8X1.9 (SM LED; 2 C-Bend Leads; Body 3.5 x 2.8 x 1.9 mm, inc leads (LxWxH typ))
simulation model Agl_HSMKA100 (Diode)
signal-integrity model LED
pins: 1 A, 2 K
